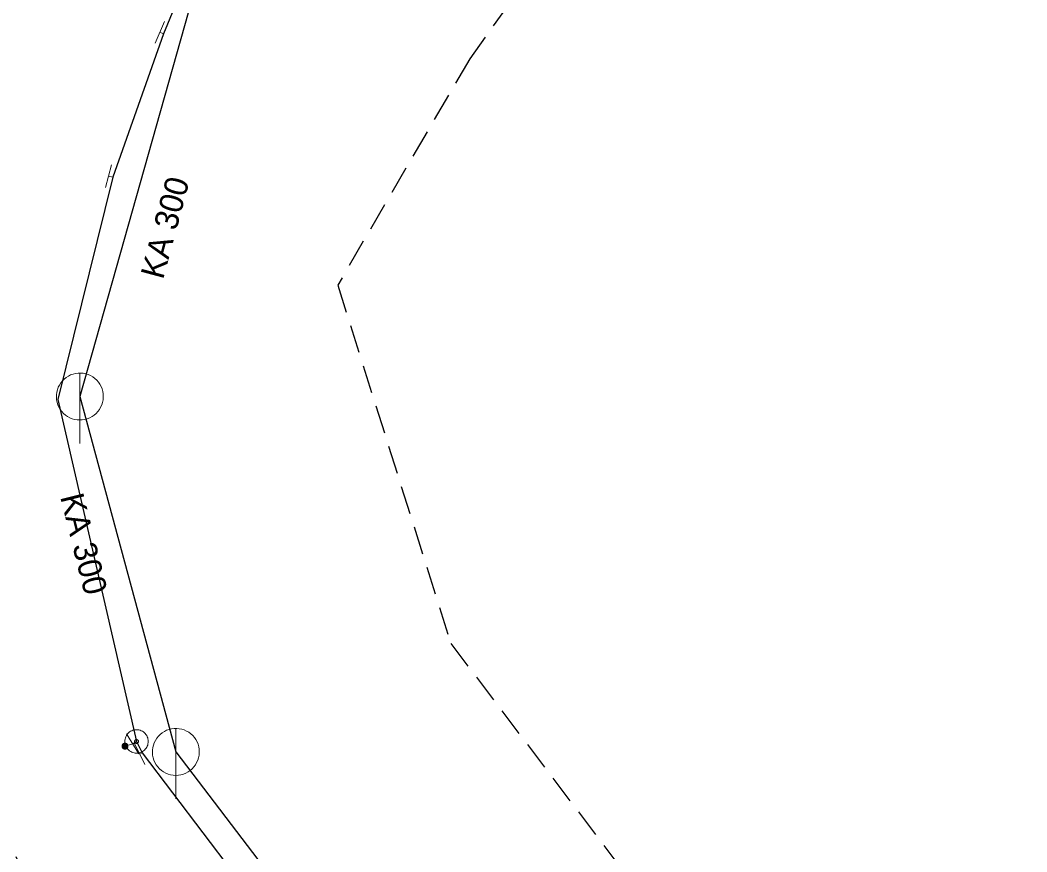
# Model space of a CAD drawing. Extents: x -686636 to -686482, y -972667 to -972167.
# Drawn here: x -686561.54 to -686518.64, y -972303.96 to -972268.52 of the extents above; entities that cross this region are included whole.
import ezdxf

# ---------------------------------------------------------------- set-up
doc = ezdxf.new("R2010")
doc.units = 0
doc.header["$LTSCALE"] = 0.4
doc.linetypes.add('MEDIUM_DASHED', pattern=[4.5, 3, -1.5])
for name, color, linetype, lineweight in [('1', 7, 'MEDIUM_DASHED', 25), ('14', 7, 'Continuous', 25), ('17', 7, 'Continuous', 25), ('22', 7, 'Continuous', 13), ('34', 7, 'Continuous', 13), ('47', 7, 'Continuous', 13), ('9', 7, 'Continuous', 13)]:
    doc.layers.add(name, color=color, linetype=linetype, lineweight=lineweight)

msp = doc.modelspace()

# ---------------------------------------------------------------- linework, layer by layer
at = {"layer": '1'}
msp.add_lwpolyline([(-686523.086, -972200.227), (-686492.539, -972167.269), (-686482.089, -972185.758), (-686542.379, -972270.164), (-686548.006, -972279.81), (-686543.183, -972295.084), (-686523.086, -972321.612), (-686521.478, -972360.197), (-686540.771, -972442.192), (-686521.478, -972473.543), (-686515.047, -972510.521), (-686519.067, -972578.85), (-686529.517, -972667.276), (-686549.614, -972665.668), (-686542.379, -972574.831), (-686589.003, -972562.773), (-686636.432, -972544.284), (-686625.981, -972525.795), (-686541.575, -972549.911), (-686539.967, -972501.678), (-686569.711, -972440.584), (-686549.614, -972329.65), (-686564.887, -972297.496), (-686572.926, -972277.399)], close=True, dxfattribs=at)
at = {"layer": '14'}
for p, q in [((-686553.889, -972266.458), (-686558.996, -972284.556)), ((-686558.996, -972284.556), (-686554.905, -972299.7)), ((-686554.905, -972299.7), (-686535.172, -972325.548))]:
    msp.add_line(p, q, dxfattribs=at)
at = {"layer": '14', "lineweight": 13}
for p, q in [((-686555.427, -972269.103), (-686555.592, -972269.032)), ((-686557.595, -972275.211), (-686557.776, -972275.164)), ((-686556.579, -972299.256), (-686556.743, -972299.356)), ((-686556.743, -972299.356), (-686557.07, -972299.456)), ((-686556.334, -972299.737), (-686556.443, -972299.792))]:
    msp.add_line(p, q, dxfattribs=at)
at = {"layer": '17'}
for points in [[(-686535.487, -972238.079), (-686538.799, -972243.136), (-686553.466, -972264.343), (-686555.427, -972269.103), (-686557.595, -972275.211), (-686559.928, -972284.685), (-686556.579, -972299.256)], [(-686556.579, -972299.256), (-686556.334, -972299.737), (-686543.419, -972316.782), (-686538.645, -972322.384), (-686533.358, -972333.116)]]:
    msp.add_lwpolyline(points, dxfattribs=at)
at = {"layer": '22'}
for p, q in [((-686558.996, -972286.556), (-686558.995, -972283.556)), ((-686554.905, -972301.7), (-686554.904, -972298.7))]:
    msp.add_line(p, q, dxfattribs=at)
for points in [[(-686557.996, -972284.556), (-686558.001, -972284.447), (-686558.019, -972284.339), (-686558.049, -972284.233), (-686558.089, -972284.132), (-686558.141, -972284.035), (-686558.203, -972283.945), (-686558.275, -972283.862), (-686558.355, -972283.788), (-686558.443, -972283.722), (-686558.537, -972283.667), (-686558.637, -972283.622), (-686558.742, -972283.589), (-686558.849, -972283.567), (-686558.958, -972283.557), (-686559.068, -972283.559), (-686559.176, -972283.573), (-686559.283, -972283.598), (-686559.386, -972283.635), (-686559.484, -972283.684), (-686559.576, -972283.742), (-686559.662, -972283.811), (-686559.739, -972283.888), (-686559.808, -972283.974), (-686559.867, -972284.066), (-686559.915, -972284.164), (-686559.952, -972284.267), (-686559.978, -972284.374), (-686559.992, -972284.482), (-686559.995, -972284.592), (-686559.985, -972284.701), (-686559.964, -972284.808), (-686559.93, -972284.912), (-686559.886, -972285.012), (-686559.831, -972285.107), (-686559.765, -972285.195), (-686559.691, -972285.275), (-686559.608, -972285.347), (-686559.518, -972285.409), (-686559.422, -972285.461), (-686559.32, -972285.502), (-686559.215, -972285.532), (-686559.107, -972285.55), (-686558.997, -972285.556), (-686558.888, -972285.55), (-686558.78, -972285.532), (-686558.675, -972285.503), (-686558.573, -972285.462), (-686558.476, -972285.41), (-686558.386, -972285.348), (-686558.303, -972285.277), (-686558.228, -972285.197), (-686558.163, -972285.109), (-686558.107, -972285.015), (-686558.063, -972284.915), (-686558.029, -972284.811), (-686558.007, -972284.703), (-686557.997, -972284.594)], [(-686553.905, -972299.7), (-686553.91, -972299.591), (-686553.928, -972299.483), (-686553.958, -972299.377), (-686553.998, -972299.276), (-686554.05, -972299.179), (-686554.112, -972299.089), (-686554.184, -972299.006), (-686554.264, -972298.932), (-686554.352, -972298.866), (-686554.446, -972298.811), (-686554.546, -972298.766), (-686554.651, -972298.733), (-686554.758, -972298.711), (-686554.867, -972298.701), (-686554.977, -972298.703), (-686555.085, -972298.717), (-686555.192, -972298.742), (-686555.295, -972298.779), (-686555.393, -972298.828), (-686555.485, -972298.886), (-686555.571, -972298.955), (-686555.648, -972299.032), (-686555.717, -972299.118), (-686555.776, -972299.21), (-686555.824, -972299.308), (-686555.861, -972299.411), (-686555.887, -972299.518), (-686555.901, -972299.626), (-686555.904, -972299.736), (-686555.894, -972299.845), (-686555.873, -972299.952), (-686555.839, -972300.056), (-686555.795, -972300.156), (-686555.74, -972300.251), (-686555.674, -972300.339), (-686555.6, -972300.419), (-686555.517, -972300.491), (-686555.427, -972300.553), (-686555.331, -972300.605), (-686555.229, -972300.646), (-686555.124, -972300.676), (-686555.016, -972300.694), (-686554.906, -972300.7), (-686554.797, -972300.694), (-686554.689, -972300.676), (-686554.584, -972300.647), (-686554.482, -972300.606), (-686554.385, -972300.554), (-686554.295, -972300.492), (-686554.212, -972300.421), (-686554.137, -972300.341), (-686554.072, -972300.253), (-686554.016, -972300.159), (-686553.972, -972300.059), (-686553.938, -972299.955), (-686553.916, -972299.847), (-686553.906, -972299.738)]]:
    msp.add_lwpolyline(points, close=True, dxfattribs=at)
at = {"layer": '34'}
for p, q in [((-686555.789, -972269.491), (-686555.393, -972268.573)), ((-686557.901, -972275.647), (-686557.649, -972274.68)), ((-686556.481, -972299.782), (-686557.003, -972298.929)), ((-686556.218, -972300.238), (-686556.666, -972299.344))]:
    msp.add_line(p, q, dxfattribs=at)
at = {"layer": '47'}
for points in [[(-686556.63, -972299.753), (-686556.578, -972299.755), (-686556.526, -972299.753), (-686556.475, -972299.744), (-686556.424, -972299.731), (-686556.375, -972299.712), (-686556.328, -972299.688), (-686556.285, -972299.659), (-686556.244, -972299.626), (-686556.207, -972299.59), (-686556.174, -972299.549), (-686556.145, -972299.505), (-686556.122, -972299.458), (-686556.103, -972299.41), (-686556.09, -972299.359), (-686556.081, -972299.307), (-686556.079, -972299.255), (-686556.081, -972299.203), (-686556.09, -972299.151), (-686556.103, -972299.101), (-686556.122, -972299.052), (-686556.146, -972299.005), (-686556.175, -972298.961), (-686556.208, -972298.92), (-686556.244, -972298.883), (-686556.285, -972298.851), (-686556.329, -972298.822), (-686556.376, -972298.798), (-686556.424, -972298.78), (-686556.475, -972298.767), (-686556.527, -972298.758), (-686556.579, -972298.756), (-686556.631, -972298.758), (-686556.683, -972298.766), (-686556.733, -972298.78), (-686556.782, -972298.799), (-686556.829, -972298.822), (-686556.873, -972298.851), (-686556.914, -972298.884), (-686556.951, -972298.921), (-686556.983, -972298.962), (-686557.012, -972299.006), (-686557.036, -972299.052), (-686557.054, -972299.101), (-686557.067, -972299.152), (-686557.076, -972299.204), (-686557.078, -972299.256), (-686557.076, -972299.308), (-686557.068, -972299.359), (-686557.054, -972299.41), (-686557.035, -972299.459), (-686557.012, -972299.506), (-686556.983, -972299.549), (-686556.95, -972299.59), (-686556.913, -972299.627), (-686556.872, -972299.66), (-686556.828, -972299.689), (-686556.782, -972299.712), (-686556.733, -972299.731), (-686556.682, -972299.744)], [(-686556.587, -972299.337), (-686556.578, -972299.338), (-686556.57, -972299.337), (-686556.562, -972299.336), (-686556.553, -972299.334), (-686556.545, -972299.33), (-686556.538, -972299.326), (-686556.53, -972299.322), (-686556.524, -972299.317), (-686556.518, -972299.31), (-686556.512, -972299.304), (-686556.507, -972299.296), (-686556.504, -972299.288), (-686556.501, -972299.281), (-686556.498, -972299.273), (-686556.497, -972299.264), (-686556.496, -972299.255), (-686556.497, -972299.247), (-686556.498, -972299.239), (-686556.5, -972299.23), (-686556.504, -972299.222), (-686556.508, -972299.215), (-686556.512, -972299.207), (-686556.517, -972299.201), (-686556.524, -972299.194), (-686556.53, -972299.189), (-686556.538, -972299.184), (-686556.546, -972299.181), (-686556.553, -972299.178), (-686556.561, -972299.175), (-686556.57, -972299.174), (-686556.579, -972299.173), (-686556.587, -972299.174), (-686556.595, -972299.175), (-686556.604, -972299.177), (-686556.612, -972299.181), (-686556.619, -972299.184), (-686556.627, -972299.189), (-686556.633, -972299.194), (-686556.64, -972299.201), (-686556.645, -972299.207), (-686556.65, -972299.215), (-686556.653, -972299.223), (-686556.656, -972299.23), (-686556.659, -972299.238), (-686556.66, -972299.247), (-686556.661, -972299.256), (-686556.66, -972299.264), (-686556.659, -972299.272), (-686556.657, -972299.281), (-686556.653, -972299.289), (-686556.65, -972299.296), (-686556.645, -972299.304), (-686556.64, -972299.31), (-686556.633, -972299.316), (-686556.627, -972299.322), (-686556.619, -972299.327), (-686556.611, -972299.33), (-686556.604, -972299.333), (-686556.596, -972299.336)]]:
    msp.add_lwpolyline(points, close=True, dxfattribs=at)
at = {"layer": '9'}
for points in [[(-686557.196, -972299.456), (-686557.196, -972299.469), (-686557.193, -972299.482), (-686557.191, -972299.495), (-686557.186, -972299.507), (-686557.179, -972299.519), (-686557.173, -972299.53), (-686557.164, -972299.54), (-686557.154, -972299.55), (-686557.144, -972299.558), (-686557.134, -972299.565), (-686557.122, -972299.571), (-686557.11, -972299.576), (-686557.097, -972299.579), (-686557.083, -972299.581), (-686557.071, -972299.583), (-686557.058, -972299.582), (-686557.044, -972299.58), (-686557.032, -972299.577), (-686557.019, -972299.572), (-686557.007, -972299.566), (-686556.997, -972299.559), (-686556.987, -972299.551), (-686556.977, -972299.541), (-686556.968, -972299.531), (-686556.962, -972299.52), (-686556.956, -972299.508), (-686556.951, -972299.496), (-686556.948, -972299.483), (-686556.946, -972299.47), (-686556.943, -972299.457), (-686556.945, -972299.444), (-686556.946, -972299.431), (-686556.95, -972299.418), (-686556.955, -972299.406), (-686556.96, -972299.394), (-686556.968, -972299.383), (-686556.975, -972299.373), (-686556.985, -972299.363), (-686556.995, -972299.355), (-686557.007, -972299.348), (-686557.019, -972299.342), (-686557.031, -972299.337), (-686557.044, -972299.334), (-686557.056, -972299.332), (-686557.07, -972299.331), (-686557.083, -972299.331), (-686557.095, -972299.333), (-686557.108, -972299.336), (-686557.12, -972299.341), (-686557.132, -972299.347), (-686557.144, -972299.354), (-686557.154, -972299.362), (-686557.164, -972299.372), (-686557.171, -972299.382), (-686557.179, -972299.393), (-686557.184, -972299.405), (-686557.19, -972299.417), (-686557.193, -972299.43), (-686557.195, -972299.443)], [(-686557.176, -972299.456), (-686557.176, -972299.467), (-686557.174, -972299.478), (-686557.171, -972299.489), (-686557.168, -972299.499), (-686557.163, -972299.509), (-686557.157, -972299.518), (-686557.149, -972299.527), (-686557.142, -972299.535), (-686557.132, -972299.542), (-686557.124, -972299.548), (-686557.114, -972299.553), (-686557.103, -972299.557), (-686557.093, -972299.56), (-686557.081, -972299.563), (-686557.071, -972299.563), (-686557.059, -972299.563), (-686557.049, -972299.561), (-686557.038, -972299.558), (-686557.027, -972299.554), (-686557.017, -972299.549), (-686557.009, -972299.543), (-686557, -972299.536), (-686556.992, -972299.528), (-686556.985, -972299.519), (-686556.978, -972299.51), (-686556.973, -972299.5), (-686556.97, -972299.49), (-686556.967, -972299.479), (-686556.965, -972299.468), (-686556.963, -972299.457), (-686556.963, -972299.446), (-686556.965, -972299.435), (-686556.968, -972299.424), (-686556.973, -972299.414), (-686556.978, -972299.404), (-686556.983, -972299.395), (-686556.99, -972299.386), (-686556.999, -972299.378), (-686557.007, -972299.371), (-686557.017, -972299.365), (-686557.027, -972299.36), (-686557.036, -972299.356), (-686557.048, -972299.353), (-686557.058, -972299.351), (-686557.07, -972299.351), (-686557.081, -972299.35), (-686557.092, -972299.352), (-686557.103, -972299.355), (-686557.112, -972299.359), (-686557.122, -972299.364), (-686557.132, -972299.37), (-686557.141, -972299.377), (-686557.149, -972299.385), (-686557.156, -972299.394), (-686557.161, -972299.403), (-686557.166, -972299.413), (-686557.171, -972299.423), (-686557.174, -972299.434), (-686557.176, -972299.445)], [(-686557.157, -972299.456), (-686557.157, -972299.465), (-686557.156, -972299.474), (-686557.152, -972299.483), (-686557.149, -972299.491), (-686557.146, -972299.499), (-686557.141, -972299.507), (-686557.134, -972299.514), (-686557.129, -972299.52), (-686557.122, -972299.526), (-686557.114, -972299.531), (-686557.105, -972299.535), (-686557.098, -972299.538), (-686557.088, -972299.541), (-686557.08, -972299.542), (-686557.071, -972299.544), (-686557.061, -972299.543), (-686557.053, -972299.542), (-686557.044, -972299.539), (-686557.036, -972299.536), (-686557.027, -972299.532), (-686557.019, -972299.527), (-686557.012, -972299.521), (-686557.007, -972299.515), (-686557, -972299.508), (-686556.995, -972299.5), (-686556.992, -972299.492), (-686556.989, -972299.484), (-686556.985, -972299.475), (-686556.985, -972299.466), (-686556.982, -972299.457), (-686556.983, -972299.448), (-686556.985, -972299.439), (-686556.987, -972299.43), (-686556.99, -972299.422), (-686556.995, -972299.414), (-686557, -972299.406), (-686557.005, -972299.399), (-686557.012, -972299.393), (-686557.019, -972299.387), (-686557.027, -972299.382), (-686557.034, -972299.378), (-686557.043, -972299.375), (-686557.051, -972299.372), (-686557.061, -972299.371), (-686557.07, -972299.37), (-686557.078, -972299.37), (-686557.088, -972299.371), (-686557.097, -972299.374), (-686557.105, -972299.377), (-686557.112, -972299.381), (-686557.12, -972299.386), (-686557.127, -972299.392), (-686557.134, -972299.398), (-686557.139, -972299.405), (-686557.144, -972299.413), (-686557.149, -972299.421), (-686557.152, -972299.429), (-686557.154, -972299.438), (-686557.156, -972299.447)], [(-686557.137, -972299.456), (-686557.137, -972299.463), (-686557.136, -972299.47), (-686557.134, -972299.477), (-686557.132, -972299.483), (-686557.129, -972299.489), (-686557.125, -972299.495), (-686557.12, -972299.501), (-686557.115, -972299.506), (-686557.11, -972299.51), (-686557.103, -972299.514), (-686557.098, -972299.517), (-686557.092, -972299.52), (-686557.085, -972299.521), (-686557.078, -972299.524), (-686557.071, -972299.524), (-686557.063, -972299.524), (-686557.056, -972299.522), (-686557.049, -972299.521), (-686557.044, -972299.518), (-686557.036, -972299.515), (-686557.032, -972299.511), (-686557.026, -972299.507), (-686557.021, -972299.502), (-686557.017, -972299.496), (-686557.012, -972299.49), (-686557.009, -972299.484), (-686557.007, -972299.478), (-686557.005, -972299.471), (-686557.004, -972299.464), (-686557.002, -972299.457), (-686557.002, -972299.45), (-686557.004, -972299.443), (-686557.005, -972299.436), (-686557.009, -972299.43), (-686557.012, -972299.423), (-686557.016, -972299.418), (-686557.019, -972299.412), (-686557.024, -972299.407), (-686557.031, -972299.403), (-686557.036, -972299.399), (-686557.043, -972299.396), (-686557.049, -972299.393), (-686557.056, -972299.391), (-686557.063, -972299.39), (-686557.07, -972299.39), (-686557.076, -972299.39), (-686557.083, -972299.39), (-686557.09, -972299.392), (-686557.097, -972299.395), (-686557.103, -972299.398), (-686557.108, -972299.402), (-686557.115, -972299.406), (-686557.12, -972299.411), (-686557.124, -972299.417), (-686557.127, -972299.422), (-686557.13, -972299.429), (-686557.134, -972299.435), (-686557.134, -972299.442), (-686557.137, -972299.449)], [(-686557.117, -972299.456), (-686557.117, -972299.461), (-686557.117, -972299.466), (-686557.115, -972299.471), (-686557.114, -972299.475), (-686557.112, -972299.48), (-686557.108, -972299.484), (-686557.105, -972299.487), (-686557.102, -972299.491), (-686557.098, -972299.494), (-686557.095, -972299.497), (-686557.09, -972299.499), (-686557.085, -972299.501), (-686557.081, -972299.502), (-686557.076, -972299.504), (-686557.071, -972299.504), (-686557.066, -972299.504), (-686557.061, -972299.503), (-686557.056, -972299.502), (-686557.051, -972299.5), (-686557.046, -972299.498), (-686557.043, -972299.495), (-686557.039, -972299.492), (-686557.036, -972299.488), (-686557.032, -972299.485), (-686557.029, -972299.481), (-686557.027, -972299.476), (-686557.026, -972299.472), (-686557.024, -972299.467), (-686557.024, -972299.462), (-686557.022, -972299.457), (-686557.022, -972299.452), (-686557.024, -972299.447), (-686557.024, -972299.442), (-686557.027, -972299.438), (-686557.029, -972299.433), (-686557.032, -972299.429), (-686557.034, -972299.425), (-686557.038, -972299.422), (-686557.041, -972299.419), (-686557.046, -972299.416), (-686557.051, -972299.414), (-686557.054, -972299.412), (-686557.059, -972299.411), (-686557.065, -972299.41), (-686557.07, -972299.41), (-686557.075, -972299.41), (-686557.08, -972299.411), (-686557.085, -972299.411), (-686557.088, -972299.413), (-686557.093, -972299.415), (-686557.098, -972299.418), (-686557.1, -972299.421), (-686557.105, -972299.424), (-686557.107, -972299.428), (-686557.11, -972299.432), (-686557.112, -972299.437), (-686557.115, -972299.441), (-686557.115, -972299.446), (-686557.117, -972299.451)], [(-686557.097, -972299.456), (-686557.097, -972299.459), (-686557.098, -972299.462), (-686557.097, -972299.464), (-686557.095, -972299.467), (-686557.095, -972299.47), (-686557.093, -972299.472), (-686557.09, -972299.474), (-686557.088, -972299.476), (-686557.087, -972299.478), (-686557.085, -972299.48), (-686557.081, -972299.482), (-686557.078, -972299.483), (-686557.076, -972299.483), (-686557.073, -972299.484), (-686557.071, -972299.484), (-686557.068, -972299.484), (-686557.065, -972299.484), (-686557.061, -972299.483), (-686557.059, -972299.482), (-686557.056, -972299.481), (-686557.054, -972299.479), (-686557.051, -972299.477), (-686557.049, -972299.475), (-686557.049, -972299.473), (-686557.046, -972299.471), (-686557.046, -972299.468), (-686557.044, -972299.465), (-686557.044, -972299.463), (-686557.043, -972299.46), (-686557.041, -972299.457), (-686557.043, -972299.454), (-686557.043, -972299.451), (-686557.044, -972299.448), (-686557.044, -972299.446), (-686557.046, -972299.443), (-686557.048, -972299.441), (-686557.049, -972299.438), (-686557.051, -972299.436), (-686557.054, -972299.435), (-686557.056, -972299.433), (-686557.058, -972299.432), (-686557.061, -972299.431), (-686557.063, -972299.43), (-686557.066, -972299.43), (-686557.07, -972299.429), (-686557.073, -972299.43), (-686557.076, -972299.429), (-686557.078, -972299.431), (-686557.081, -972299.431), (-686557.083, -972299.432), (-686557.085, -972299.434), (-686557.088, -972299.435), (-686557.09, -972299.437), (-686557.092, -972299.44), (-686557.093, -972299.442), (-686557.095, -972299.445), (-686557.095, -972299.447), (-686557.097, -972299.45), (-686557.097, -972299.453)], [(-686557.078, -972299.456), (-686557.078, -972299.458), (-686557.078, -972299.458), (-686557.076, -972299.458), (-686557.076, -972299.46), (-686557.078, -972299.461), (-686557.076, -972299.461), (-686557.076, -972299.461), (-686557.076, -972299.463), (-686557.076, -972299.463), (-686557.075, -972299.464), (-686557.073, -972299.464), (-686557.073, -972299.464), (-686557.073, -972299.465), (-686557.071, -972299.465), (-686557.071, -972299.465), (-686557.07, -972299.465), (-686557.068, -972299.465), (-686557.068, -972299.464), (-686557.068, -972299.464), (-686557.066, -972299.464), (-686557.066, -972299.463), (-686557.066, -972299.463), (-686557.065, -972299.462), (-686557.065, -972299.462), (-686557.063, -972299.461), (-686557.063, -972299.46), (-686557.061, -972299.459), (-686557.061, -972299.459), (-686557.061, -972299.458), (-686557.061, -972299.457), (-686557.061, -972299.456), (-686557.061, -972299.455), (-686557.061, -972299.455), (-686557.063, -972299.454), (-686557.063, -972299.453), (-686557.063, -972299.452), (-686557.063, -972299.452), (-686557.065, -972299.451), (-686557.065, -972299.451), (-686557.066, -972299.45), (-686557.066, -972299.45), (-686557.068, -972299.449), (-686557.068, -972299.449), (-686557.068, -972299.449), (-686557.07, -972299.449), (-686557.071, -972299.449), (-686557.071, -972299.449), (-686557.071, -972299.449), (-686557.073, -972299.45), (-686557.073, -972299.449), (-686557.075, -972299.451), (-686557.075, -972299.451), (-686557.076, -972299.451), (-686557.076, -972299.451), (-686557.076, -972299.453), (-686557.076, -972299.454), (-686557.076, -972299.455), (-686557.078, -972299.455), (-686557.078, -972299.456)]]:
    msp.add_lwpolyline(points, close=True, dxfattribs=at)

# ---------------------------------------------------------------- texts
at = {"layer": '1'}
for rotation, p in [(75, (-686555.45, -972279.602)), (284, (-686559.836, -972288.824))]:
    msp.add_text('KA 300', height=1, rotation=rotation, dxfattribs=at).set_placement(p)

doc.saveas('drawing.dxf')
